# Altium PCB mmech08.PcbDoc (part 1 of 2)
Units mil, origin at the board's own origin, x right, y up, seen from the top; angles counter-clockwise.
Board outline 2098.43 x 3200 mil, 4 copper layers (Top Layer, Ground Plane, Mid Layer 1, Bottom Layer), stack 59.851 mil thick; 121 components, 87 nets, 440 pads, 296 vias.
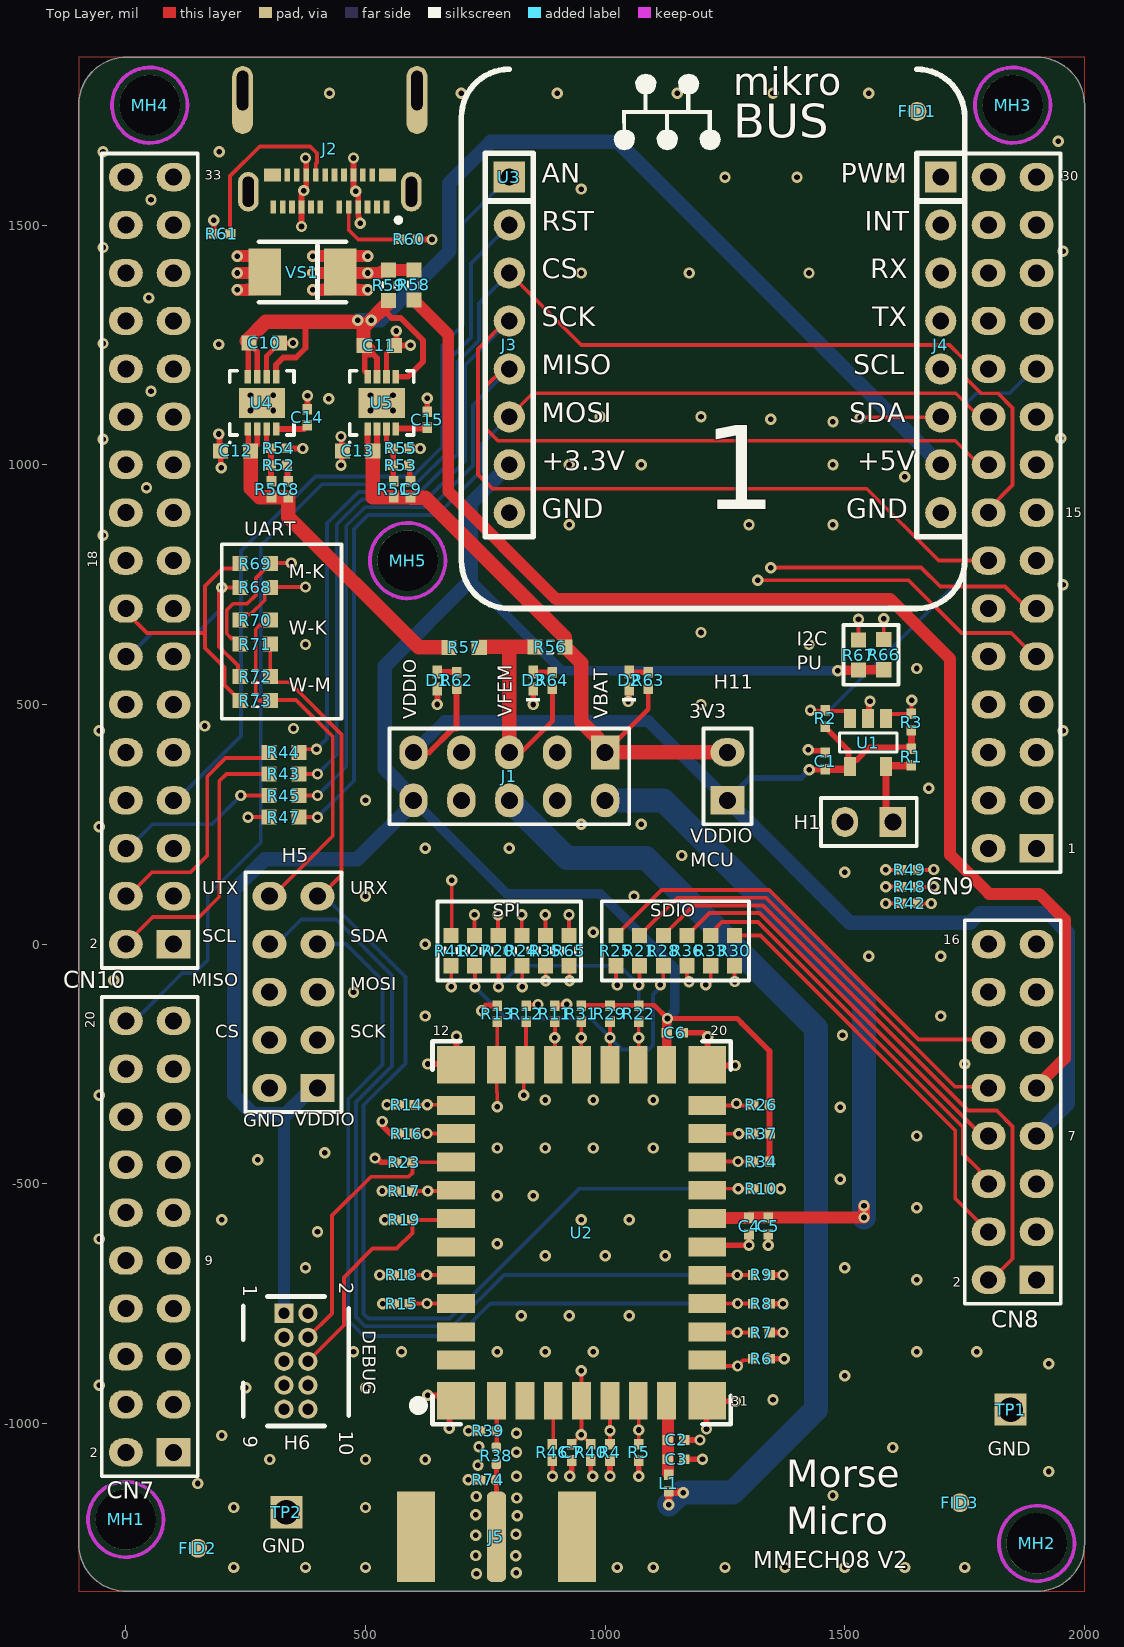
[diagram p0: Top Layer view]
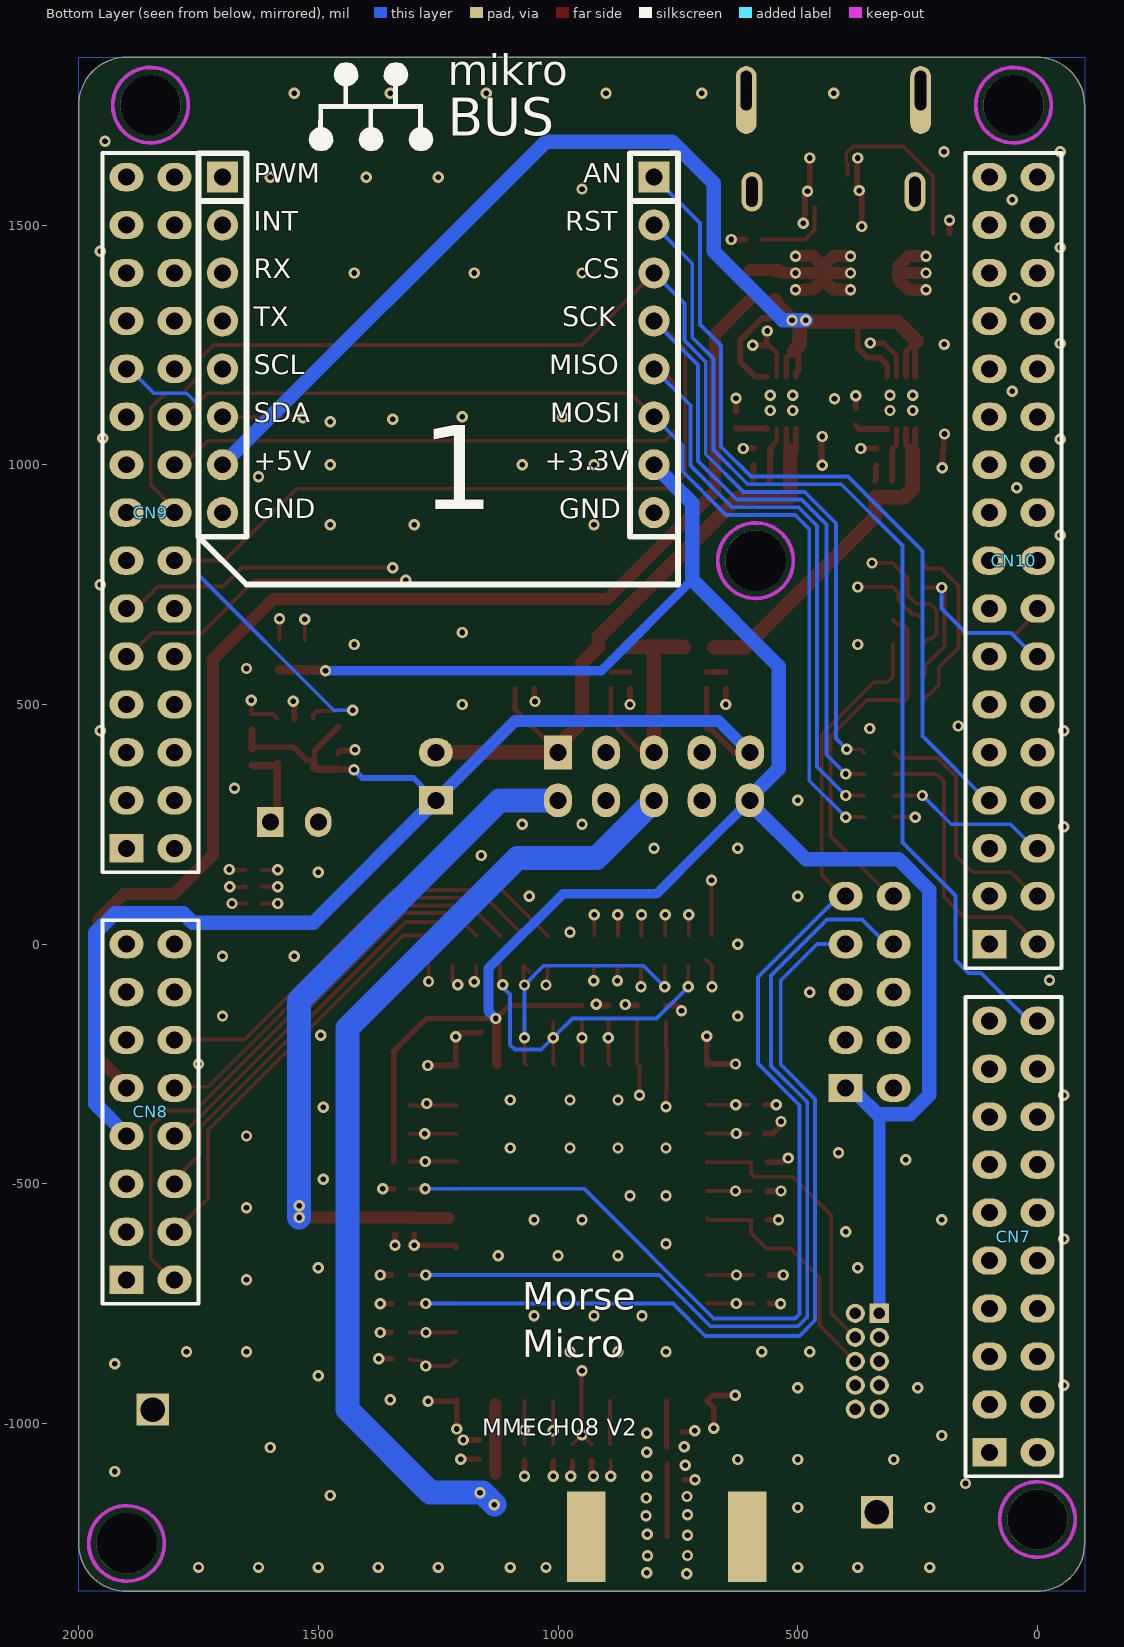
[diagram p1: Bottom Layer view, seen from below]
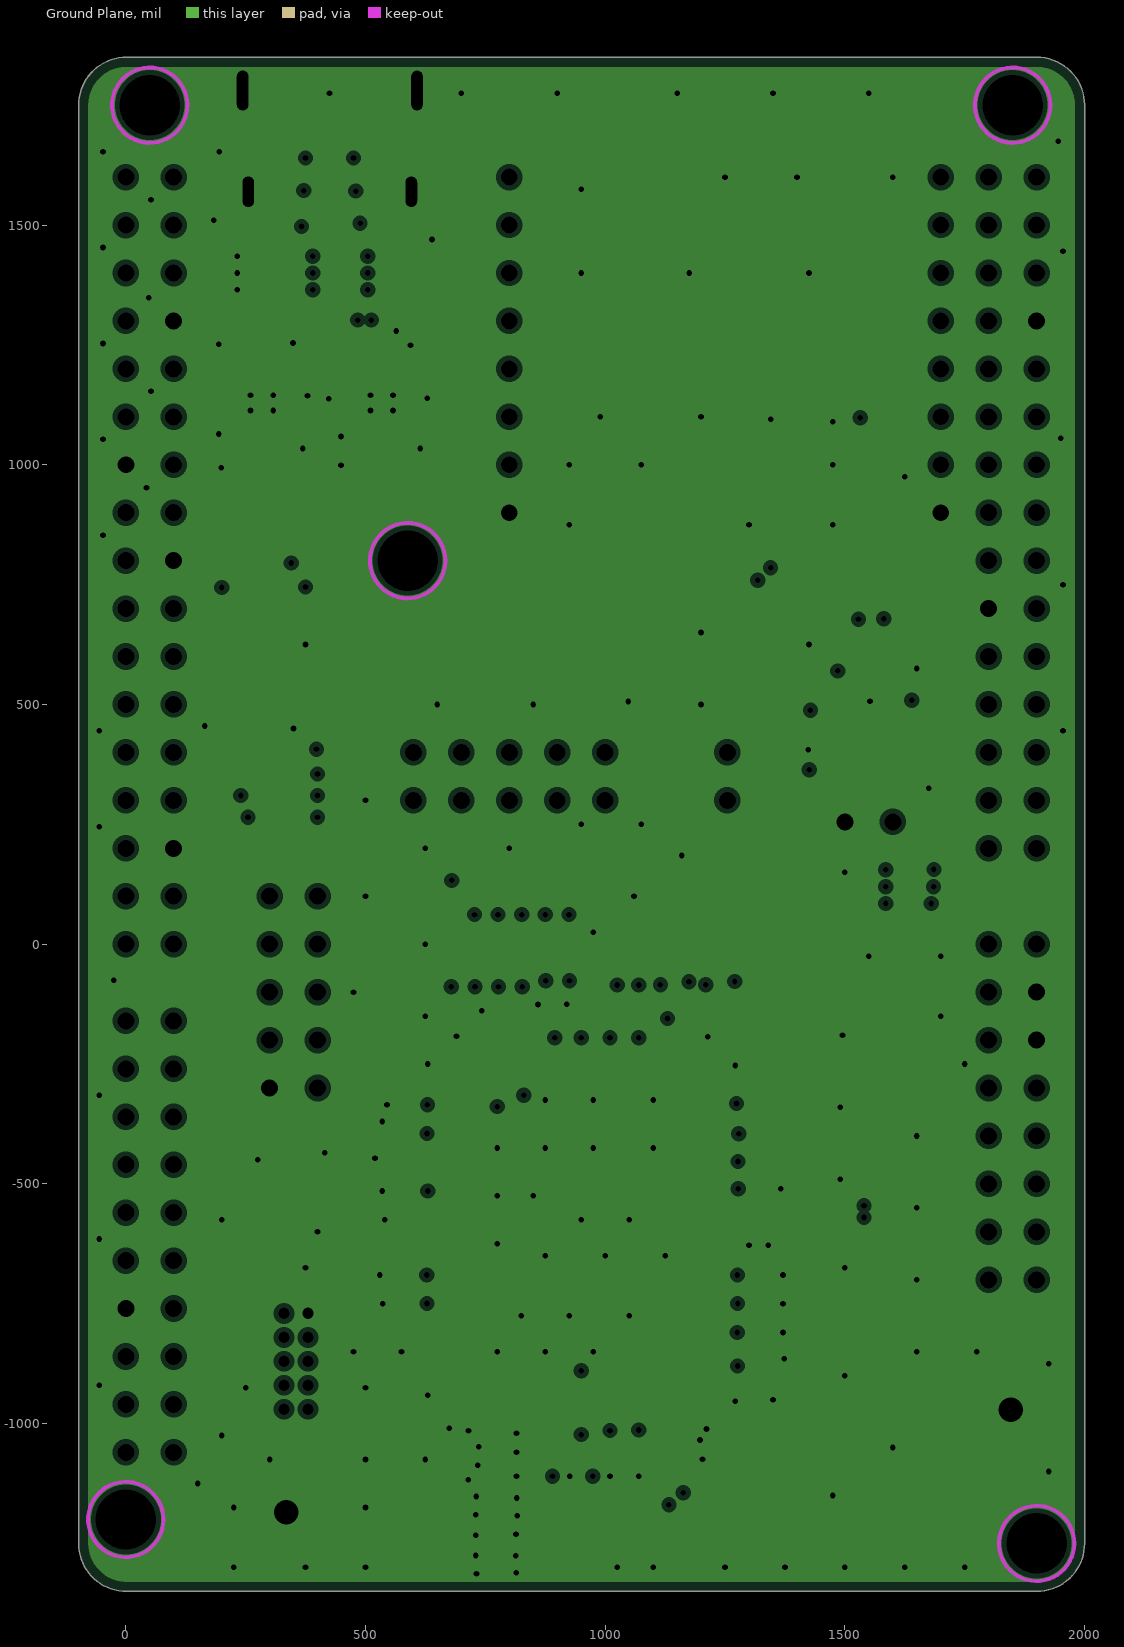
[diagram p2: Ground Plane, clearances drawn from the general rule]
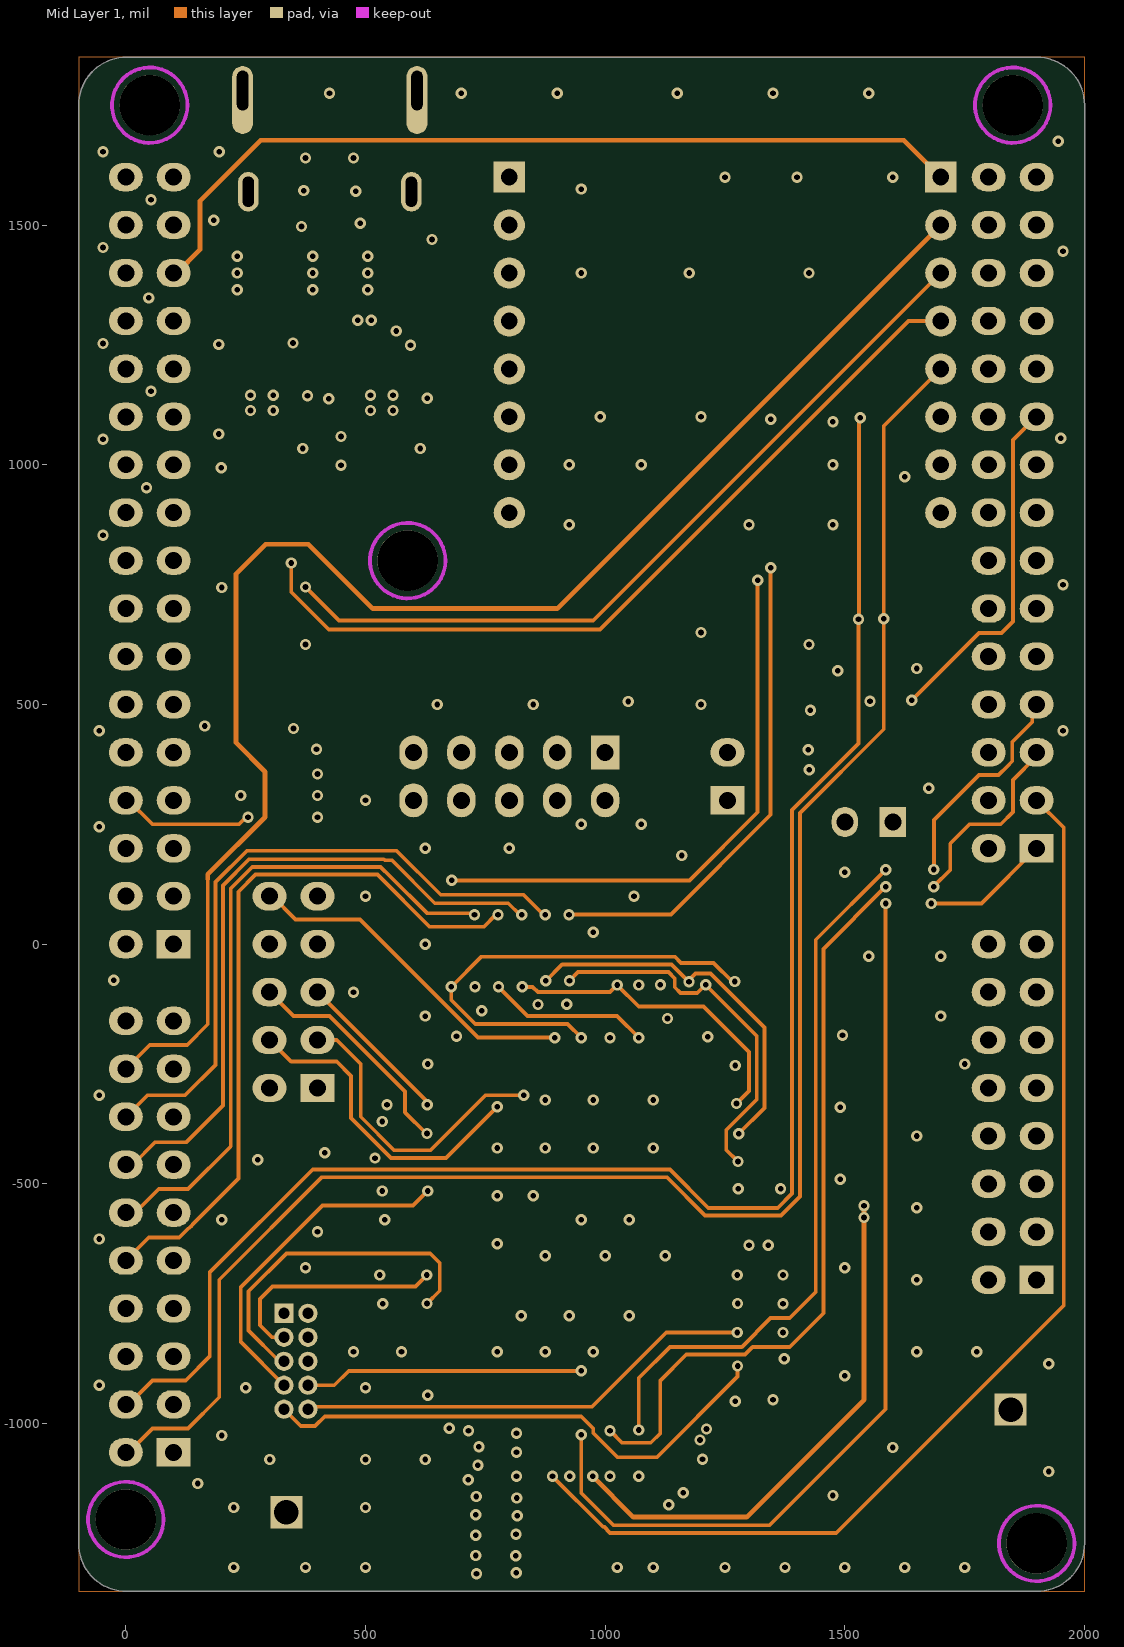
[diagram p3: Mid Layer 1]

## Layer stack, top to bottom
Top Solder: solder mask 0.787, SM-001, Dk 4.2
Top Layer: signal copper 1.378
Dielectric 1: prepreg 6.5, PP, Dk 4.29
Ground Plane: plane copper 1.378, net GND
Dielectric 2: core 41.3386, Core, Dk 4.29
Mid Layer 1: signal copper 1.378
Dielectric 3: prepreg 6.5, PP, Dk 4.29
Bottom Layer: signal copper 1.378
Bottom Solder: solder mask 0.787, SM-001, Dk 4.2

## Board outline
-98.37,-1250 -98.37,1750 cw(c1.63,1750) 1.63,1850 1900.05,1850 cw(c1900.05,1750) 2000.05,1750 2000.05,-1250 2000.02,-1250 cw(c1900.02,-1250) 1900.02,-1350 1.63,-1350 cw(c1.63,-1250)

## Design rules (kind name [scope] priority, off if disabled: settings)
AssemblyTestPointUsage [All] p0 off: scope1count=1 scope1_0_kind=Board scope1_0_value=Board scope2count=1 scope2_0_kind=Board scope2_0_value=Board commentlength=0
AssemblyTestPointUsage [All] p1 off:
AssemblyTestpoint [All] p0 off: scope1count=1 scope1_0_kind=Board scope1_0_value=Board scope2count=1 scope2_0_kind=Board scope2_0_value=Board commentlength=0
AssemblyTestpoint [All] p1 off: testpointundercomponent=TRUE minsize=40 maxsize=100 preferedsize=60 minholesize=0 maxholesize=40 preferedholesize=32 testpointgrid=1 usegrid=TRUE gridtolerance=0.01 allowsidetop=TRUE allowsidebottom=TRUE
BoardOutlineClearance [All] p0 off: scope1count=1 scope1_0_kind=Board scope1_0_value=Board scope2count=1 scope2_0_kind=Board scope2_0_value=Board commentlength=129 gap=20 // Protel DXP Scope 1 Expression Was: (not OnTopSilkscreen) AND (NOT OnBottomSilkscreen) and (not OnMultiLayer) and (not IsText)
BoardOutlineClearance [(not OnTopSilkscreen) AND (NOT OnBottomSilkscreen) and (not OnMultiLayer) and (not IsText)] p1: gap=20 ignorepadtopadclearanceinfootprint=FALSE
Clearance "RF Clearance" [All] p0 off: scope1count=1 scope1_0_kind=NetClass scope1_0_value=RF-Net scope2count=1 scope2_0_kind=Board scope2_0_value=Board commentlength=48 gap=10 // Protel DXP Scope 2 Expression Was: InPolygon
Clearance "Schematic Clearance Constraint_2" [All] p0: scope1count=1 scope1_0_kind=Component scope1_0_value=FID3 scope2count=1 scope2_0_kind=Board scope2_0_value=Board commentlength=0 gap=0
Clearance "Schematic Clearance Constraint_1" [All] p0: scope1count=1 scope1_0_kind=Component scope1_0_value=FID2 scope2count=1 scope2_0_kind=Board scope2_0_value=Board commentlength=0 gap=0
Clearance "Schematic Clearance Constraint" [All] p0: scope1count=1 scope1_0_kind=Component scope1_0_value=FID1 scope2count=1 scope2_0_kind=Board scope2_0_value=Board commentlength=0 gap=0
Clearance Clearance_U4_U5_J2 [All] p0: scope1count=1 scope1_0_kind=Component scope1_0_value=J2','U4','U5 scope2count=1 scope2_0_kind=Board scope2_0_value=Board commentlength=0 gap=6
Clearance [All] p0: scope1count=1 scope1_0_kind=Board scope1_0_value=Board scope2count=1 scope2_0_kind=Board scope2_0_value=Board commentlength=0 gap=8
Clearance "RF Clearance" [InNetClass('RF-Net') vs InPolygon] p1: gap=10 ignorepadtopadclearanceinfootprint=TRUE
Clearance "Schematic Clearance Constraint_2" [InComponent('FID3')] p2: gap=0 ignorepadtopadclearanceinfootprint=FALSE
Clearance "Schematic Clearance Constraint_1" [InComponent('FID2')] p3: gap=0 ignorepadtopadclearanceinfootprint=FALSE
Clearance "Schematic Clearance Constraint" [InComponent('FID1')] p4: gap=0 ignorepadtopadclearanceinfootprint=FALSE
Clearance Clearance_U4_U5_J2 [InComponent('J2','U4','U5')] p5: gap=6 ignorepadtopadclearanceinfootprint=TRUE
Clearance [All] p6: gap=8 ignorepadtopadclearanceinfootprint=TRUE
ComponentClearance [All] p0 off: scope1count=1 scope1_0_kind=Board scope1_0_value=Board scope2count=1 scope2_0_kind=Board scope2_0_value=Board commentlength=0 gap=10 collisioncheckmode=3
ComponentClearance [All] p1 off: gap=10 collisioncheckmode=3 verticalgap=10 showdistances=FALSE
DiffPairsRouting [All] p0 off: scope1count=1 scope1_0_kind=Board scope1_0_value=Board scope2count=1 scope2_0_kind=Board scope2_0_value=Board commentlength=0
DiffPairsRouting [All] p1 off: maxlimit=10 minlimit=10 mostfreqgap=10 toplayer_minwidth=15 toplayer_maxwidth=15 toplayer_prefwidth=15 midlayer3_minwidth=15 midlayer3_maxwidth=15 midlayer3_prefwidth=15 bottomlayer_minwidth=15 bottomlayer_maxwidth=15 bottomlayer_prefwidth=15 maxuncoupledlength=500
FabricationTestPointUsage [All] p0 off: scope1count=1 scope1_0_kind=Board scope1_0_value=Board scope2count=1 scope2_0_kind=Board scope2_0_value=Board commentlength=0 valid=0 allowmultiple=FALSE
FabricationTestPointUsage [All] p1 off: valid=0 allowmultiple=FALSE
FabricationTestpoint [All] p0 off: scope1count=1 scope1_0_kind=Board scope1_0_value=Board scope2count=1 scope2_0_kind=Board scope2_0_value=Board commentlength=0 side=3 testpointundercomponent=TRUE minsize=40 maxsize=100 preferedsize=60 minholesize=0 maxholesize=40 preferedholesize=32 testpointgrid=1
FabricationTestpoint [All] p1 off: side=3 testpointundercomponent=TRUE minsize=40 maxsize=100 preferedsize=60 minholesize=0 maxholesize=40 preferedholesize=32 testpointgrid=1 allowsidetop=TRUE allowsidebottom=TRUE usegrid=TRUE gridtolerance=0.01
FanoutControl Fanout_BGA [All] p0 off: scope1count=1 scope1_0_kind=Board scope1_0_value=Board scope2count=1 scope2_0_kind=Board scope2_0_value=Board commentlength=69 // Protel DXP Scope 1 Expression Was: IsBGA   Fanout_BGA (Default Rule)
FanoutControl Fanout_LCC [All] p0 off: scope1count=1 scope1_0_kind=Board scope1_0_value=Board scope2count=1 scope2_0_kind=Board scope2_0_value=Board commentlength=69 // Protel DXP Scope 1 Expression Was: IsLCC   Fanout_LCC (Default Rule)
FanoutControl Fanout_SOIC [All] p0 off: scope1count=1 scope1_0_kind=Board scope1_0_value=Board scope2count=1 scope2_0_kind=Board scope2_0_value=Board commentlength=71 // Protel DXP Scope 1 Expression Was: IsSOIC   Fanout_SOIC (Default Rule)
FanoutControl Fanout_Small [All] p0 off: scope1count=1 scope1_0_kind=Board scope1_0_value=Board scope2count=1 scope2_0_kind=Board scope2_0_value=Board commentlength=84 // Protel DXP Scope 1 Expression Was: (CompPinCount < 5)   Fanout_Small (Default Rule)
FanoutControl Fanout_Default [All] p0 off: scope1count=1 scope1_0_kind=Board scope1_0_value=Board scope2count=1 scope2_0_kind=Board scope2_0_value=Board commentlength=30 // Fanout_Default (Default Rule)
FanoutControl Fanout_BGA [IsBGA] p1 off: bgadir=Out bgaviamode=Centered fanoutstyle=Auto fanoutdirection=Alternating viagrid=1 // Fanout_BGA (Default Rule)
FanoutControl Fanout_LCC [IsLCC] p2 off: bgadir=Out bgaviamode=Centered fanoutstyle=Auto fanoutdirection=Alternating viagrid=1 // Fanout_LCC (Default Rule)
FanoutControl Fanout_SOIC [IsSOIC] p3 off: bgadir=Out bgaviamode=Centered fanoutstyle=Auto fanoutdirection=Alternating viagrid=1 // Fanout_SOIC (Default Rule)
FanoutControl Fanout_Small [(CompPinCount < 5)] p4 off: bgadir=Out bgaviamode=Centered fanoutstyle=Auto fanoutdirection=OutThenIn viagrid=1 // Fanout_Small (Default Rule)
FanoutControl Fanout_Default [All] p5 off: bgadir=Out bgaviamode=Centered fanoutstyle=Auto fanoutdirection=Alternating viagrid=1 // Fanout_Default (Default Rule)
Height "POGO Pins" [All] p0: scope1count=1 scope1_0_kind=ComponentClass scope1_0_value=POGO scope2count=1 scope2_0_kind=Board scope2_0_value=Board commentlength=0
Height TP1 [All] p0: scope1count=1 scope1_0_kind=Component scope1_0_value=TP1 scope2count=1 scope2_0_kind=Board scope2_0_value=Board commentlength=0
Height "Under Socket" [All] p0 off: scope1count=1 scope1_0_kind=Board scope1_0_value=Board scope2count=1 scope2_0_kind=Board scope2_0_value=Board commentlength=64 // Protel DXP Scope 1 Expression Was: WithinRoom('ROOM_SOCKET')
Height [All] p0 off: scope1count=1 scope1_0_kind=Board scope1_0_value=Board scope2count=1 scope2_0_kind=Board scope2_0_value=Board commentlength=0
Height TP1 [InComponent('TP1')] p1: minheight=0 maxheight=472.44 prefheight=118.11
Height "POGO Pins" [InComponentClass('POGO')] p2: minheight=0 maxheight=275.59 prefheight=196.85
Height "Under Socket" [WithinRoom('ROOM_SOCKET')] p3: minheight=0 maxheight=157.48 prefheight=118.11
Height [All] p4 off: minheight=0 maxheight=1000 prefheight=500
HoleSize [All] p0: scope1count=1 scope1_0_kind=Board scope1_0_value=Board scope2count=1 scope2_0_kind=Board scope2_0_value=Board commentlength=0 absolutevalues=TRUE maxlimit=200 minlimit=8 maxpercent=80.000 minpercent=20.000
HoleSize [All] p1: absolutevalues=TRUE maxlimit=200 minlimit=8 maxpercent=80.000 minpercent=20.000
HoleToHoleClearance [All] p0: scope1count=1 scope1_0_kind=Board scope1_0_value=Board scope2count=1 scope2_0_kind=Board scope2_0_value=Board commentlength=0
HoleToHoleClearance [All] p1: gap=8 allowstackedmicrovias=TRUE
LayerPairs [All] p0 off: scope1count=1 scope1_0_kind=Board scope1_0_value=Board scope2count=1 scope2_0_kind=Board scope2_0_value=Board commentlength=0 enforce=TRUE
LayerPairs [All] p1 off: enforce=TRUE
MatchedLengths MatchLengths_U1_Passives_J5_1 [All] p0 off: scope1count=1 scope1_0_kind=Board scope1_0_value=Board scope2count=1 scope2_0_kind=Board scope2_0_value=Board commentlength=100 tolerance=50 amplitude=200 gap=20 style=90-Degree // Protel DXP Scope 1 Expression Was: InxSignalClass('xSignals_U1_Passives_J5_MatchLengthsClass_1')
MatchedLengths MatchLengths_U1_Passives_J5 [All] p0 off: scope1count=1 scope1_0_kind=Board scope1_0_value=Board scope2count=1 scope2_0_kind=Board scope2_0_value=Board commentlength=98 tolerance=50 amplitude=200 gap=20 style=90-Degree // Protel DXP Scope 1 Expression Was: InxSignalClass('xSignals_U1_Passives_J5_MatchLengthsClass')
MatchedLengths MatchLengths_U1_Passives_J5_1 [InxSignalClass('xSignals_U1_Passives_J5_MatchLengthsClass_1')] p1: tolerance=50 checknetsindiffpair=FALSE checkdiffpairvsdiffpair=TRUE checkxsignals=TRUE checkothers=TRUE
MatchedLengths MatchLengths_U1_Passives_J5 [InxSignalClass('xSignals_U1_Passives_J5_MatchLengthsClass')] p2: tolerance=50 checknetsindiffpair=FALSE checkdiffpairvsdiffpair=TRUE checkxsignals=TRUE checkothers=TRUE
MinimumSolderMaskSliver [All] p0 off: scope1count=1 scope1_0_kind=Board scope1_0_value=Board scope2count=1 scope2_0_kind=Board scope2_0_value=Board commentlength=96 // Protel DXP Scope 1 Expression Was: not InComponent('U4','U1','U5','U6','U7','U8','U9','U10')
MinimumSolderMaskSliver [not InComponent('U4','U1','U5','U6','U7','U8','U9','U10')] p1: minsoldermaskwidth=3
NetAntennae [All] p0: scope1count=1 scope1_0_kind=Board scope1_0_value=Board scope2count=1 scope2_0_kind=Board scope2_0_value=Board commentlength=0
PasteMaskExpansion [All] p0: scope1count=1 scope1_0_kind=Board scope1_0_value=Board scope2count=1 scope2_0_kind=Board scope2_0_value=Board commentlength=0 expansion=0
PlaneClearance [All] p0: scope1count=1 scope1_0_kind=Board scope1_0_value=Board scope2count=1 scope2_0_kind=Board scope2_0_value=Board commentlength=0 clearance=10
PlaneClearance [All] p1: clearance=10
PlaneConnect [All] p0: scope1count=1 scope1_0_kind=Board scope1_0_value=Board scope2count=1 scope2_0_kind=Board scope2_0_value=Board commentlength=0 planeconnectstyle=Relief reliefexpansion=20 reliefentries=4 reliefconductorwidth=10 reliefairgap=10
PlaneConnect [All] p1: pad.planeconnectstyle=Relief pad.reliefexpansion=20 pad.reliefentries=4 pad.reliefconductorwidth=10 pad.reliefairgap=10 via.planeconnectstyle=Direct via.reliefexpansion=20 via.reliefentries=4 via.reliefconductorwidth=10 via.reliefairgap=10
PolygonConnect "Schematic Polygon Connect Style" [All] p0: scope1count=1 scope1_0_kind=Component scope1_0_value=J5 scope2count=1 scope2_0_kind=Board scope2_0_value=Board commentlength=0 connectstyle=Direct reliefconductorwidth=10 reliefentries=4 polygonreliefangle="45 Angle"
PolygonConnect [All] p0: scope1count=1 scope1_0_kind=Board scope1_0_value=Board scope2count=1 scope2_0_kind=Board scope2_0_value=Board commentlength=0 connectstyle=Relief reliefconductorwidth=10 reliefentries=4 polygonreliefangle="90 Angle"
PolygonConnect "Schematic Polygon Connect Style" [InComponent('J5')] p1: connectstyle=Direct reliefconductorwidth=10 reliefentries=4 polygonreliefangle="45 Angle" airgapwidth=10
PolygonConnect [All] p2: thpad.connectstyle=Relief thpad.reliefconductorwidth=10 thpad.reliefentries=4 thpad.polygonreliefangle="90 Angle" thpad.airgapwidth=10 smdpad.connectstyle=Direct smdpad.reliefconductorwidth=10 smdpad.reliefentries=4 smdpad.polygonreliefangle="90 Angle" smdpad.airgapwidth=10 via.connectstyle=Direct via.reliefconductorwidth=10 via.reliefentries=4 via.polygonreliefangle="90 Angle" via.airgapwidth=10
RoutingCorners [All] p0: scope1count=1 scope1_0_kind=Board scope1_0_value=Board scope2count=1 scope2_0_kind=Board scope2_0_value=Board commentlength=0 cornerstyle=45-Degree minsetback=100 maxsetback=100
RoutingLayers [All] p0: scope1count=1 scope1_0_kind=Board scope1_0_value=Board scope2count=1 scope2_0_kind=Board scope2_0_value=Board commentlength=0 top layer=Automatic mid layer 3=Automatic bottom layer=Automatic
RoutingPriority [All] p0: scope1count=1 scope1_0_kind=Board scope1_0_value=Board scope2count=1 scope2_0_kind=Board scope2_0_value=Board commentlength=0
RoutingTopology [All] p0: scope1count=1 scope1_0_kind=Board scope1_0_value=Board scope2count=1 scope2_0_kind=Board scope2_0_value=Board commentlength=0 topology=Shortest
RoutingVias [All] p0: scope1count=1 scope1_0_kind=Board scope1_0_value=Board scope2count=1 scope2_0_kind=Board scope2_0_value=Board commentlength=0 holewidth=8 width=20 viastyle="Through Hole" minholewidth=8 minwidth=20 maxholewidth=28 maxwidth=50
RoutingVias [All] p1: holewidth=8 width=20 viastyle="Through Hole" minholewidth=8 minwidth=20 maxholewidth=28 maxwidth=50
ShortCircuit [All] p0: scope1count=1 scope1_0_kind=Board scope1_0_value=Board scope2count=1 scope2_0_kind=Board scope2_0_value=Board commentlength=0 allowed=FALSE
SilkToBoardRegionClearance [All] p0: scope1count=1 scope1_0_kind=Board scope1_0_value=Board scope2count=1 scope2_0_kind=Board scope2_0_value=Board commentlength=0
SilkToSilkClearance [All] p0 off: scope1count=1 scope1_0_kind=Board scope1_0_value=Board scope2count=1 scope2_0_kind=Board scope2_0_value=Board commentlength=0
SilkToSilkClearance [All] p1 off: silktosilkclearance=8
SilkToSolderMaskClearance [All] p0 off: scope1count=1 scope1_0_kind=Board scope1_0_value=Board scope2count=1 scope2_0_kind=Board scope2_0_value=Board commentlength=44 // Protel DXP Scope 1 Expression Was: IsPad
SilkToSolderMaskClearance [IsPad] p1 off: minsilkscreentomaskgap=4 clearancetoexposedcopper=TRUE
SolderMaskExpansion [All] p0: scope1count=1 scope1_0_kind=Board scope1_0_value=Board scope2count=1 scope2_0_kind=Board scope2_0_value=Board commentlength=0 expansion=4
SolderMaskExpansion [All] p1: expansion=4 istentingtop=FALSE
SupplyNets SupplyNets_7 [All] p0: scope1count=1 scope1_0_kind=Net scope1_0_value=VDD_PA scope2count=1 scope2_0_kind=Board scope2_0_value=Board commentlength=0 voltage=4.000
SupplyNets SupplyNets_6 [All] p0: scope1count=1 scope1_0_kind=Net scope1_0_value=VDD_LNA scope2count=1 scope2_0_kind=Board scope2_0_value=Board commentlength=0 voltage=4.000
SupplyNets SupplyNets_5 [All] p0: scope1count=1 scope1_0_kind=Net scope1_0_value=VDD_FEM scope2count=1 scope2_0_kind=Board scope2_0_value=Board commentlength=0 voltage=4.000
SupplyNets SupplyNets_4 [All] p0: scope1count=1 scope1_0_kind=Net scope1_0_value=VDD5_RPi scope2count=1 scope2_0_kind=Board scope2_0_value=Board commentlength=0 voltage=5.000
SupplyNets SupplyNets_3 [All] p0: scope1count=1 scope1_0_kind=Net scope1_0_value=VDD5 scope2count=1 scope2_0_kind=Board scope2_0_value=Board commentlength=0 voltage=5.000
SupplyNets SupplyNets_2 [All] p0: scope1count=1 scope1_0_kind=Net scope1_0_value=VBAT scope2count=1 scope2_0_kind=Board scope2_0_value=Board commentlength=0 voltage=3.300
SupplyNets SupplyNets_1 [All] p0: scope1count=1 scope1_0_kind=Net scope1_0_value=VDD33 scope2count=1 scope2_0_kind=Board scope2_0_value=Board commentlength=0 voltage=3.300
SupplyNets [All] p0: scope1count=1 scope1_0_kind=Net scope1_0_value=GND scope2count=1 scope2_0_kind=Board scope2_0_value=Board commentlength=0 voltage=0.000
SupplyNets SupplyNets_1 [InNet('VDD33')] p1: voltage=3.300
SupplyNets SupplyNets_2 [InNet('VBAT')] p2: voltage=3.300
SupplyNets SupplyNets_3 [InNet('VDD5')] p3: voltage=5.000
SupplyNets SupplyNets_4 [InNet('VDD5_RPi')] p4: voltage=5.000
SupplyNets SupplyNets_5 [InNet('VDD_FEM')] p5: voltage=4.000
SupplyNets SupplyNets_6 [InNet('VDD_LNA')] p6: voltage=4.000
SupplyNets SupplyNets_7 [InNet('VDD_PA')] p7: voltage=4.000
SupplyNets [InNet('GND')] p8: voltage=0.000
UnConnectedPin [All] p0 off: scope1count=1 scope1_0_kind=Board scope1_0_value=Board scope2count=1 scope2_0_kind=Board scope2_0_value=Board commentlength=0
UnConnectedPin [All] p1 off:
UnRoutedNet [All] p0: scope1count=1 scope1_0_kind=Board scope1_0_value=Board scope2count=1 scope2_0_kind=Board scope2_0_value=Board commentlength=0
UnRoutedNet [All] p1: checkbadconnections=TRUE
UnpouredPolygon [All] p0: scope1count=1 scope1_0_kind=Board scope1_0_value=Board scope2count=1 scope2_0_kind=Board scope2_0_value=Board commentlength=0
Width "RF Width" [All] p0: scope1count=1 scope1_0_kind=NetClass scope1_0_value=RF-Net scope2count=1 scope2_0_kind=Board scope2_0_value=Board commentlength=0 maxlimit=50 minlimit=7 preferedwidth=8
Width [All] p0: scope1count=1 scope1_0_kind=Board scope1_0_value=Board scope2count=1 scope2_0_kind=Board scope2_0_value=Board commentlength=0 maxlimit=50 minlimit=8 preferedwidth=8
Width [All] p1: maxlimit=50 minlimit=8 preferedwidth=8
Width "RF Width" [InNetClass('RF-Net')] p2: maxlimit=50 minlimit=7 preferedwidth=8 toplayer_maxwidth=7 toplayer_prefwidth=10 impedanceprofiledriven=TRUE impedanceprofileid={2BAD1660-FF1E-4629-AB45-93BC2CD73358} impedanceprofilevalue=50.000000 minimp=50.000000 maximp=50.000000 favimp=50.000000
9 further rules are at their usual default settings.

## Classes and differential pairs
net class RF-Net: NetJ5_1 NetR38_1
component class CHIP_OTHER: C10 C11 C12 C13 D1 D2 D3 R20 R21 R24 R25 R27 R28 R30 R33 R35 R36 R41 R43 R44 R45 R47 R56 R57 R58 R59 R65 R66 R67 R68 R69 R70 R71 R72 R73
component class MMECH08_Power: C8 C9 C10 C11 C12 C13 C14 C15 D1 D2 D3 FID1 FID2 FID3 H11 J1 J2 MH1 MH2 MH3 MH4 MH5 R50 R51 R52 R53 R54 R55 R56 R57 R58 R59 R60 R61 R62 R63 R64 TP1 TP2 U4 U5 VS1
component class CHIP_MICRO: C1 C2 C3 C4 C5 C6 C7 C8 C9 C14 C15 L1 R1 R2 R3 R4 R5 R6 R7 R8 R9 R10 R11 R12 R13 R14 R15 R16 R17 R18 R19 R22 R23 R26 R29 R31 R34 R37 R38 R39 R40 R42 R46 R48 R49 R50 R51 R52 R53 R54 R55 R60 R61 R62 R63 R64 R74
component class MMECH08_Module_Interfaces: C1 C2 C3 C4 C5 C6 C7 CN7 CN8 CN9 CN10 H1 H5 H6 J3 J4 J5 L1 R1 R2 R3 R4 R5 R6 R7 R8 R9 R10 R11 R12 R13 R14 R15 R16 R17 R18 R19 R20 R21 R22 R23 R24 R25 R26 R27 R28 R29 R30 R31 R33 R34 R35 R36 R37 R38 R39 R40 R41 R42 R43 R44 R45 R46 R47 R48 R49 R65 R66 R67 R68 R69 R70 R71 R72 R73 R74 U1 U2 U3
component class PCB_PATTERN: FID1 FID2 FID3 FID7 FID8 MH1 MH2 MH3 MH4 MH5
component class COMP_OTHER: CN7 CN8 CN9 CN10 H1 H5 H6 H11 J1 J2 J3 J4 J5 TP1 TP2 U1 U2 U3 U4 U5 VS1

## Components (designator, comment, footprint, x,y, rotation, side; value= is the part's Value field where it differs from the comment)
C1 "CAP" 0402_CAP 1458.63,382 r90 top
C2 "CAP" 0402_CAP 1147.84,-1034.16 r0 top
C3 "CAP" 0402_CAP 1147.84,-1074.16 r0 top
C4 "CAP" 0402_CAP 1300,-588 r90 top
C5 "CAP" 0402_CAP 1340,-588 r270 top
C6 "CAP" 0402_CAP 1145,-185 r0 top
C7 "CAP" 0402_CAP 930,-1060 r270 top
C8 "CAP_DNF" 0402_cap_dnf 338.94,949 r90 top
C9 "CAP_DNF" 0402_cap_dnf 593.94,949 r90 top
C10 "CAP" 0603_cap 288.94,1254 r0 top
C11 "CAP" 0603_cap 528.88,1249 r0 top
C12 "CAP" 0603_cap 228.94,1029 r180 top
C13 "CAP" 0603_cap 483.94,1029 r180 top
C14 "CAP" 0402_cap 378.94,1099 r90 top
C15 "CAP" 0402_cap 628.95,1094 r90 top
CN7 ".Designator" HDR2X10 100,-1060 r90 bottom
CN8 ".Designator" HDR2X8 1900,-700 r90 bottom
CN9 ".Designator" HDR2X15 1900,200 r90 bottom
CN10 ".Designator" HDR2X17 100,0 r90 bottom
D1 "LED_G" LED_0402_GREEN 650,550 r270 top
D2 "LED_G" LED_0402_GREEN 1050,550 r270 top
D3 "LED_G" LED_0402_GREEN 850,550 r270 top
FID1 "FIDUCIAL" FIDUCIAL_1MM 1650.63,1737 r0 top
FID2 "FIDUCIAL" FIDUCIAL_1MM 150,-1260 r0 top
FID3 "FIDUCIAL" FIDUCIAL_1MM 1740,-1165 r90 top
H1 "HDR_1X2_DNF" HDR1X2_DNF 1600,255 r180 top
H5 "HDR_2X5" HDR2X5 400,-300 r90 top
H6 "2X5_FTSH_DV_K" FTSH_105_D_K 355,-870 r270 top
H11 "HDR_1X2" HDR1X2 1255,300 r90 top
J1 "HDR_2X5" HDR2X5 1000,400 r180 top
J2 "CONN RCP USB3.1 TYPEC 24P SMD RA" USB-C_RCP 425.63,1659 r180 top
J3 "75915-308LF * 2" 75915-308LF 800,1600 r0 top
J4 "75915-308LF" 75915-308LF 1700,1600 r0 top
J5 "SMA-EDGE" SMA_RA-EDGE 773.27,-1350 r0 top
L1 "IND" 0402_ind 1132.84,-1124.16 r270 top
MH1 "MH_360_320_NPTH" MH_360_320_NPTH 0.02,-1200 r0 top locked
MH2 "MH_360_320_NPTH" MH_360_320_NPTH 1900.02,-1250 r0 top locked
MH3 "MH_360_320_NPTH" MH_360_320_NPTH 1850.02,1750 r0 top locked
MH4 "MH_360_320_NPTH" MH_360_320_NPTH 50.02,1750 r0 top locked
MH5 "MH_360_320_NPTH" MH_360_320_NPTH 588.02,800 r0 top locked
R1 "RES" 0402_RES#1 1638.63,390.63 r270 top
R2 "RES" 0402_RES#1 1458.63,471 r90 top
R3 "RES" 0402_RES#1 1638.63,463.16 r90 top
R4 "RES" 0402_RES#1 1010,-1060 r270 top
R5 "RES" 0402_res 1070,-1060 r270 top
R6 "RES" 0402_RES#1 1325.84,-865 r0 top
R7 "RES" 0402_RES#1 1325.84,-810 r0 top
R8 "RES" 0402_RES#1 1325.84,-750 r0 top
R9 "RES" 0402_RES#1 1325.84,-690 r0 top
R10 "RES" 0402_RES#1 1325.84,-510 r0 top
R11 "RES" 0402_RES#1 895,-145 r90 top
R12 "RES" 0402_RES#1 835,-145 r90 top
R13 "RES" 0402_RES#1 775,-145 r90 top
R14 "RES" 0402_RES#1 585.84,-335 r180 top
R15 "RES" 0402_RES#1 575.84,-750 r180 top
R16 "RES" 0402_RES#1 585.84,-395 r180 top
R17 "RES_DNF" 0402_res_dnf#1 580.84,-515 r180 top
R18 "RES" 0402_RES#1 575.84,-690 r180 top
R19 "RES" 0402_RES#1 580.84,-575 r180 top
R20 "RES" 0603_res 776.91,-13.5 r270 top
R21 "RES_DNF" 0603_res_dnf 1071.75,-13.5 r90 top
R22 "RES" 0402_RES#1 1070,-145 r270 top
R23 "RES" 0402_RES#1 580.84,-455 r180 top
R24 "RES" 0603_res 826.2,-13.5 r270 top
R25 "RES_DNF" 0603_res_dnf 1022.28,-13.5 r90 top
R26 "RES" 0402_RES#1 1325.84,-335 r180 top
R27 "RES" 0603_res 727.61,-13.5 r270 top
R28 "RES_DNF" 0603_res_dnf 1121.22,-13.5 r90 top
R29 "RES" 0402_RES#1 1010,-145 r90 top
R30 "RES_DNF" 0603_res_dnf 1269.63,-13.5 r90 top
R31 "RES" 0402_RES#1 950,-145 r90 top
R33 "RES_DNF" 0603_res_dnf 1220.16,-13.5 r90 top
R34 "RES" 0402_RES#1 1325.84,-453.39 r0 top
R35 "RES" 0603_res 875.5,-13.5 r270 top
R36 "RES_DNF" 0603_res_dnf 1170.69,-13.5 r90 top
R37 "RES" 0402_RES#1 1325.84,-395 r180 top
R38 "RES" 0402_RES#2 773,-1067 r270 top
R39 "RES_DNF" 0402_res_dnf#2 756.13,-1015.12 r180 top
R40 "RES" 0402_RES#1 970,-1060 r90 top
R41 "RES" 0603_res 678.32,-13.5 r270 top
R42 "RES" 0402_res 1635,85 r0 top
R43 "RES_DNF" 0603_res_dnf 330,355 r0 top
R44 "RES_DNF" 0603_res_dnf 330,400 r0 top
R45 "RES_DNF" 0603_res_dnf 330,310 r0 top
R46 "RES" 0402_res 890,-1060 r270 top
R47 "RES_DNF" 0603_res_dnf 330,265 r0 top
R48 "RES" 0402_res 1635,120 r0 top
R49 "RES" 0402_res 1635,155 r0 top
R50 "RES" 0402_res 303.94,949 r90 top
R51 "RES" 0402_res 558.94,949 r90 top
R52 "RES_DNF" 0402_res_dnf#1 318.94,999 r0 top
R53 "RES_DNF" 0402_res_dnf#1 573.94,999 r0 top
R54 "RES" 0402_res 318.94,1034 r0 top
R55 "RES" 0402_res 573.94,1034 r0 top
R56 "RES" 0603_res 885,620 r180 top
R57 "RES_DNF" 0603_res_dnf 705.75,619.17 r0 top
R58 "RES" 0603_res 600.83,1375.09 r270 top
R59 "RES" 0603_res 548.29,1374.35 r270 top
R60 "RES" 0402_RES#1 591.63,1470 r0 top
R61 "RES" 0402_RES#1 200.63,1482 r180 top
R62 "RES" 0402_RES#1 690,550 r270 top
R63 "RES" 0402_RES#1 1090,550 r270 top
R64 "RES" 0402_res 890,550 r270 top
R65 "RES" 0603_res 924.79,-13.5 r270 top
R66 "RES_DNF" 0603_res_dnf 1581,604 r90 top
R67 "RES_DNF" 0603_res_dnf 1528.47,603.07 r90 top
R68 "RES_DNF" 0603_res_dnf 270,744 r180 top
R69 "RES_DNF" 0603_res_dnf 270,794 r180 top
R70 "RES_DNF" 0603_res_dnf 270,676 r0 top
R71 "RES_DNF" 0603_res_dnf 270,626 r0 top
R72 "RES" 0603_res 270,558 r0 top
R73 "RES" 0603_res 270,508 r0 top
R74 "RES_DNF" 0402_res_dnf#2 756.13,-1117.12 r180 top
TP1 "TP-BLK" TP-100_BLACK 1845.47,-970.93 r0 top
TP2 "TP-BLK" TP-100_BLACK 335,-1185 r0 top
U1 "AT24C32D" SOT-23_5 1548.63,420.63 r270 top
U2 "MM61xx-MF04151" MF04 950.84,-601.97 r90 top locked
U3 "MIKROBUS_Host" MIKROBUS_Host_SD 800,1600 r0 top
U4 "ADM7172" PSON50P300X80_HS-9N 283.94,1129 r90 top
U5 "ADM7172" PSON50P300X80_HS-9N 533.94,1129 r90 top
VS1 "Varistor_Uni" DO-214AC 368.63,1402 r0 top

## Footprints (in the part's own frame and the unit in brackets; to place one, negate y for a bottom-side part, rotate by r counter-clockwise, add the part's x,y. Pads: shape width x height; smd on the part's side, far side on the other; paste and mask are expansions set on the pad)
0402_CAP [mil]
  rect 22x20 smd: 1(-17,0) 2(17,0)
0402_cap [mil]
  rect 22x20 smd: 1(-17,0) 2(17,0)
0402_cap_dnf [mil]
  rect 22x20 smd paste-196.85: 1(-17,0) 2(17,0)
0402_ind [mil]
  rect 22x20 smd: 1(-17,0) 2(17,0)
0402_RES#1 [mil]
  rect 22x20 smd: 1(-17,0) 2(17,0)
0402_RES#2 [mil]
  rrect50% 22x20 smd: 1(-17,0) 2(17,0)
0402_res [mil]
  rect 22x20 smd: 1(-17,0) 2(17,0)
0402_res_dnf#1 [mil]
  rect 22x20 smd paste-196.85: 1(-17,0) 2(17,0)
0402_res_dnf#2 [mil]
  rrect50% 22x20 smd paste-196.85: 1(-17,0)
  rect 22x20 smd paste-196.85: 2(17,0)
0603_cap [mm]
  rect 0.8x0.8 smd: 1(-0.8,0) 2(0.8,0)
0603_res [mm]
  rect 0.8x0.8 smd: 1(-0.8,0) 2(0.8,0)
  silkscreen extent -0.15,-0.33 0.15,0.33
0603_res_dnf [mm]
  rect 0.8x0.8 smd paste-10: 1(-0.8,0) 2(0.8,0)
75915-308LF [mil] "CONN RCPT 8POS 0.1 GOLD PCB"
  rect 65x65 hole 35: 1(0,0)
  round 65 hole 35: 2(0,-100) 3(0,-200) 4(0,-300) 5(0,-400) 6(0,-500) 7(0,-600) 8(0,-700)
  silkscreen extent -50,-750 50,50
DO-214AC [mm]
  rect 1.7x2.5 smd: A(-2,0) K(2,0)
  silkscreen extent -2.3,-1.6 2.3,1.6
FIDUCIAL_1MM [mm]
  round 1 smd paste-1 mask+0: 1(0,0)
FTSH_105_D_K [mil]
  rect 40x40 hole 23.62 mask+0: 1(-100,-25)
  round 40 hole 23.62 mask+0: 2(-100,25) 3(-50,-25) 4(-50,25) 5(0,-25) 6(0,25) 7(50,-25) 8(50,25) 9(100,-25) 10(100,25)
  silkscreen extent -135,-110 135,110
HDR1X2 [mm] "Connector; Header; 2 Position"
  rect 1.5x1.8 hole 0.9: 1(0,0)
  oval 1.5x1.8 hole 0.9: 2(2.54,0)
  silkscreen extent -1.27,-1.27 3.81,1.27
HDR1X2_DNF [mm] "Connector; Header; 2 Position"
  rect 1.4x1.6 hole 0.9: 1(0,0)
  oval 1.4x1.6 hole 0.9: 2(2.54,0)
  silkscreen extent -1.27,-1.27 3.81,1.27
HDR2X5 [mm] "Connector; Header; 5x2 Position"
  rect 1.5x1.8 hole 0.9: 1(0,0)
  oval 1.5x1.8 hole 0.9: 2(0,2.54) 3(2.54,0) 4(2.54,2.54) 5(5.08,0) 6(5.08,2.54) 7(7.62,0) 8(7.62,2.54) 9(10.16,0) 10(10.16,2.54)
  silkscreen extent -1.27,-1.27 11.43,3.81
HDR2X8 [mm] "Connector; Header; 8x2 Position"
  rect 1.5x1.8 hole 0.9: 1(0,0)
  oval 1.5x1.8 hole 0.9: 2(0,-2.54) 3(2.54,0) 4(2.54,-2.54) 5(5.08,0) 6(5.08,-2.54) 7(7.62,0) 8(7.62,-2.54) 9(10.16,0) 10(10.16,-2.54) 11(12.7,0) 12(12.7,-2.54) 13(15.24,0) 14(15.24,-2.54) 15(17.78,0) 16(17.78,-2.54)
  silkscreen extent -1.27,-3.81 19.05,1.27
HDR2X10 [mm] "Connector; Header; 10x2 Position"
  rect 1.5x1.8 hole 0.9: 1(0,0)
  oval 1.5x1.8 hole 0.9: 2(0,-2.54) 3(2.54,0) 4(2.54,-2.54) 5(5.08,0) 6(5.08,-2.54) 7(7.62,0) 8(7.62,-2.54) 9(10.16,0) 10(10.16,-2.54) 11(12.7,0) 12(12.7,-2.54) 13(15.24,0) 14(15.24,-2.54) 15(17.78,0) 16(17.78,-2.54) 17(20.32,0) 18(20.32,-2.54) 19(22.86,0) 20(22.86,-2.54)
  silkscreen extent -1.27,-3.81 24.13,1.27
HDR2X15 [mm] "Connector; Header; 15x2 Position"
  rect 1.5x1.8 hole 0.9: 1(0,0)
  oval 1.5x1.8 hole 0.9: 2(0,-2.54) 3(2.54,0) 4(2.54,-2.54) 5(5.08,0) 6(5.08,-2.54) 7(7.62,0) 8(7.62,-2.54) 9(10.16,0) 10(10.16,-2.54) 11(12.7,0) 12(12.7,-2.54) 13(15.24,0) 14(15.24,-2.54) 15(17.78,0) 16(17.78,-2.54) 17(20.32,0) 18(20.32,-2.54) 19(22.86,0) 20(22.86,-2.54) 21(25.4,0) 22(25.4,-2.54) 23(27.94,0) 24(27.94,-2.54) 25(30.48,0) 26(30.48,-2.54) 27(33.02,0) 28(33.02,-2.54) 29(35.56,0) 30(35.56,-2.54)
  silkscreen extent -1.27,-3.81 36.83,1.27
HDR2X17 [mm] "Connector; Header; 17x2 Position"
  rect 1.5x1.8 hole 0.9: 1(0,0)
  oval 1.5x1.8 hole 0.9: 2(0,-2.54) 3(2.54,0) 4(2.54,-2.54) 5(5.08,0) 6(5.08,-2.54) 7(7.62,0) 8(7.62,-2.54) 9(10.16,0) 10(10.16,-2.54) 11(12.7,0) 12(12.7,-2.54) 13(15.24,0) 14(15.24,-2.54) 15(17.78,0) 16(17.78,-2.54) 17(20.32,0) 18(20.32,-2.54) 19(22.86,0) 20(22.86,-2.54) 21(25.4,0) 22(25.4,-2.54) 23(27.94,0) 24(27.94,-2.54) 25(30.48,0) 26(30.48,-2.54) 27(33.02,0) 28(33.02,-2.54) 29(35.56,0) 30(35.56,-2.54) 31(38.1,0) 32(38.1,-2.54) 33(40.64,0) 34(40.64,-2.54)
  silkscreen extent -1.27,-3.81 41.91,1.27
LED_0402_GREEN [mm]
  rect 0.7x0.5 smd: A(-0.45,0) K(0.45,0)
MF04 [mm]
  rect 2x2 smd: 1(-8.9,6.65) 12(8.9,6.65) 20(8.9,-6.65) 31(-8.9,-6.65)
  rect 1x2 smd: 2(-6.75,6.65) 3(-5.25,6.65) 4(-3.75,6.65) 5(-2.25,6.65) 6(-0.75,6.65) 7(0.75,6.65) 8(2.25,6.65) 9(3.75,6.65) 10(5.25,6.65) 11(6.75,6.65) 21(6.75,-6.65) 22(5.25,-6.65) 23(3.75,-6.65) 24(2.25,-6.65) 25(0.75,-6.65) 26(-0.75,-6.65) 27(-2.25,-6.65) 28(-3.75,-6.65) 29(-5.25,-6.65) 30(-6.75,-6.65)
  rect 2x1 smd: 13(8.9,4.5) 14(8.9,3) 15(8.9,1.5) 16(8.9,0) 17(8.9,-1.5) 18(8.9,-3) 19(8.9,-4.5) 32(-8.9,-4.5) 33(-8.9,-3) 34(-8.9,-1.5) 35(-8.9,0) 36(-8.9,1.5) 37(-8.9,3) 38(-8.9,4.5)
  silkscreen extent -10.15,-7.9 10.15,8.9
MH_360_320_NPTH [mm] "Non-plated mount hole 3.2mm hole 3.60mm diameter"
  round 3.2 hole 3.2 unplated mask+0: 1(0,0)
  Keep-Out Layer circle w0.2: c0,0 r2
MIKROBUS_Host_SD [mil] "MIKROBUS HOST SOCKET"
  silkscreen extent -100,-900 950,225
PSON50P300X80_HS-9N [mm] "PSON, 8-Leads, Body 3.00x3.00mm, Pitch 0.50mm, Thermal Pad 2.44x1.60mm, IPC Medium Density"
  rect 0.7x0.35 smd mask+0: 1(-1.385,0.75) 2(-1.385,0.25) 3(-1.385,-0.25) 4(-1.385,-0.75) 5(1.385,-0.75) 6(1.385,-0.25) 7(1.385,0.25) 8(1.385,0.75)
  rect 1.6x2.44 smd mask+0: EP(0,0)
  silkscreen extent -2.15,-1.7 1.7,1.75
SMA_RA-EDGE [mil]
  rrect50% 39.37x188 smd: 1(0,114)
  rect 80x188 smd: 2(-168,114) 2(168,114)
  rect 80x188 smd far side: 2(-168,114) 2(168,114)
SOT-23_5 [mil]
  rect 39x25 smd: 1(-50,37.5) 2(-50,0) 3(-50,-37.5) 4(50,-37.5) 5(50,37.5)
  silkscreen extent -20,-60 20,60
TP-100_BLACK [mm]
  rect 1.7x1.7 hole 1.3: 1(0,0)
USB-C_RCP [mm] "CONN RCP USB3.1 TYPEC 24P SMD RA"
  rect 0.3x0.7 smd mask+0: A1(-3,3.085) A2(-2.5,3.085) A3(-2,3.085) A4(-1.5,3.085) A5(-1,3.085) A6(-0.5,3.085) A7(0.5,3.085) A8(1,3.085) A9(1.5,3.085) A10(2,3.085) A11(2.5,3.085) A12(3,3.085) B2(2.25,1.385) B3(1.75,1.385) B4(1.25,1.385) B5(0.75,1.385) B6(0.25,1.385) B7(-0.25,1.385) B8(-0.75,1.385) B9(-1.25,1.385) B10(-1.75,1.385) B11(-2.25,1.385)
  rect 0.9x0.7 smd mask+0: B1(3.05,1.385) B12(-3.05,1.385)
  oval 1.1x2.1 hole 0.6 slot 1.6 at 90 deg: SH1(-4.32,2.275) SH2(4.32,2.275)
  oval 1.1x3.6 hole 0.6 slot 2.1 at 90 deg copper offset 0,0.5: SH3(4.62,-3.085) SH4(-4.62,-3.085)
  silkscreen extent -3.76,3.65 -3.51,3.9

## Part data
C1 C2 C4 C6: library part CAP0084, "Cap,100nF,10V,+/-10%,X7R,0402"
C3 C5: library part CAP0014, "CAP CER 10UF 10V 20% X5R 0402"
C7: library part CAP0023, "CAP CER 2.2UF 25V 20% X5R 0402"
C8 C9: library part CAP0049, "Update Later"
C10 C11 C12 C13: library part CAP0164, "CAP CER 10UF 25V 20% X5R 0603"
C14 C15: library part CAP0078, "Cap,1nF,50V,+/-10%,X7R,0402, RoHS"
CN7: library part HDR0019, "Conn Straight Header 10x2 0.100\" 20 POS"
CN8: library part HDR0015, "Conn Straight Header 8x2 0.100\" 16 POS"
CN9: library part HDR0027, "Conn Straight Header 15x2 0.100\" 30 POS"
CN10: library part HDR0029, "Conn Straight Header 17x2 0.100\" 32 POS"
D1 D2 D3: library part DIO0046, "LED GREEN 0402 SMD"
FID1 FID2 FID3: library part PAD0013, "1mm Round Fiducial, 0.5mm Space"
H1: library part HDR0098, "Conn Straight Header 2x1 0.100\" 2 POS (DNF)"
H5 J1: library part HDR0012, "Conn Straight Header 5x2 0.100\" 10 POS"
H6: library part HDR0090, "CONN,Vertical FTSH Series,0.05\"10 Pins, Through Hole"
H11: library part HDR0006, "Conn Straight Header 2x1 0.100\" 2 POS"
J2: library part CON0045
J3 J4: library part CON0063, "CONN RCPT 8POS 0.1 GOLD PCB"
J5: library part CON0004, "Conn SMA Right Angel .187\" Female Socket"
L1: library part IND0083, "BEAD 60OHMS 2500MA 32 MOHM"
MH1 MH2 MH3 MH4 MH5: library part PAD0034, "MH NPTH 3.60mm DIA 3.20mm HOLE"
R1: library part RES0004, "RES SMD 1Kohm 1% 1/10W Thick film 0402"
R2 R3: library part RES0204, "RES SMD 3.9K OHM 1% 1/16W 0402"
R4 R5 R6 R7 R8 R9 R10 R11 R12 R13 R14 R15 R16 R18 R19 R23 R46: library part RES0002, "RES SMD 10Kohm 1% 1/10W Thick film 0402"
R17 R39 R52 R53 R74: library part RES0034, "Update Later"
R20 R24 R27 R35 R41 R56 R58 R59 R65 R72 R73: library part RES0119, "Res, 0 Ohm, 1/10W,+/-5%,0603 RoHS"
R21 R25 R28 R30 R33 R36 R43 R44 R45 R47 R57 R66 R67 R68 R69 R70 R71: library part RES0035, "Update Later"
R22 R26 R29 R31 R34 R37: library part RES0086, "Res, 47K Ohms,1/16W, 1%, 0402,SMD RoHS"
R38 R42 R48 R49: library part RES0001, "RES SMD 0ohm 1% 1/10W Thick film 0402"
R40: library part RES0064, "Res, 220k Ohms, 1/16W, 1%, 0402,SMD"
R50 R51: library part RES0042, "Res, 1k Ohms, 1/16W, 1%, 0402,SMD"
R54 R55: library part RES0043, "Res,10K Ohms,1/16W, 1%, 0402,SMD RoHS"
R60 R61: library part RES0094, "Res, 5.1K Ohms, 1/16W, 1%, 0402,SMD"
R62 R63 R64: library part RES0073, "Res, 330 Ohms, 1/16W, 1%, 0402,SMD"
TP1 TP2: library part CON0001, "Test Point PCB, BLACK 0.040\"D"
U1: library part ICT0181, "IC EEPROM 32KBIT I2C SOT23-5"
U2: library part MOD0007, "MM61xx-MF04"
U3: library part MOD0012, "MIKROBUS Module"
U4 U5: library part REG0068, "IC REG LINEAR POS 3.0 2A 8LFCSP"
VS1: library part DIO0056, "TVS DIODE 6V 10.3V DO214AC"

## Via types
v1: diameter 23.62, hole 11.81, Top Layer to Bottom Layer, tented both sides, 296 vias

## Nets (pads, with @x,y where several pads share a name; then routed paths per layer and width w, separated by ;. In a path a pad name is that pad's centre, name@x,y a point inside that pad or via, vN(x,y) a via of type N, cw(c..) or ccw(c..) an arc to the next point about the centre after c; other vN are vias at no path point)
5V_USB: J2.A4 J2.A9 J2.B4 J2.B9 R58.1 R59.1 VS1.K | length 835.1
  Top Layer w12: 366.58,1517.74 366.58,1497.05 v1(366.63,1497) 366.63,1537.49 J2.A9@366.58,1537.54 366.58,1566.95 v1(371.5,1571.87) 376.42,1576.79 J2.B4@376.42,1604.47 376.42,1638.58 v1(375,1640) ; v1(475,1640) 474.84,1639.84 J2.B9@474.84,1604.47 474.94,1604.38 474.94,1575.69 v1(479.81,1570.82) 484.68,1565.95 J2.A4@484.68,1537.54 ; J2.A4@484.68,1529.76 484.68,1517.74 486.59,1515.84 486.59,1506.03 v1(488.81,1503.81)
  Top Layer w25: v1(390,1365) 410.37,1365 410.66,1365.29 426.41,1365.29 VS1.K@447.37,1386.25 ; v1(390,1400) 445.37,1400 VS1.K@447.37,1402 ; v1(390,1435) 426.41,1435 VS1.K@447.37,1414.04 ; v1(504.74,1365) 484.37,1365 484.08,1365.29 468.33,1365.29 VS1.K@447.37,1386.25 ; v1(504.74,1435) 468.33,1435 VS1.K@447.37,1414.04 ; R59.1@538.83,1406.59 R58.1@600.83,1406.59 ; R59.1@548.29,1405.85 545.05,1402.6 533,1402.6 530.4,1400 449.37,1400 VS1.K@447.37,1402 ; VS1.K@447.37,1386.25 VS1.K@447.37,1402 ; VS1.K@447.37,1386.25 VS1.K@447.37,1402 ; VS1.K@447.37,1402 VS1.K@447.37,1414.04
  other v1: 504.74,1400
CC1: J2.A5 R60.1 | length 168.2
  Top Layer w8: J2.A5@463.09,1535.64 J2.A5@465,1537.54 465,1490 485,1470 545.69,1470 R60.1@574.63,1470
CC2: J2.B5 R61.1 | length 379.1
  Top Layer w8: R61.1@217.63,1482 217.63,1602 279.44,1663.81 384.86,1663.81 398.81,1649.86 398.81,1630.14 396.1,1627.43 J2.B5@396.1,1604.47
EEPROM_SCL: CN9.19 R3.2 U1.1 | length 813.5
  Top Layer w8: U1.1@1586.13,470.63 1586.13,471.66 1594.63,480.16 R3.2@1638.63,480.16 1639.13,480.66 1639.13,508.5 v1(1639.63,509)
  Mid Layer 1 w8: v1(1639.63,509) 1779.63,649 1826.63,649 1850.63,673 1850.63,1052 1898.63,1100 CN9.19@1900,1100
EEPROM_SDA: CN9.21 R2.2 U1.3 | length 1066.7
  Top Layer w8: v1@1430.25,488 R2.2@1458.63,488 1460.5,486.13 1502.63,486.13 1511.13,477.63 U1.3@1511.13,470.63
  Bottom Layer w8: v1(1428.07,487.82) 1467.82,487.82 1750,770 1750,1124.45 1774.55,1149 1843.09,1149 1894.09,1200 CN9.21@1900,1200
